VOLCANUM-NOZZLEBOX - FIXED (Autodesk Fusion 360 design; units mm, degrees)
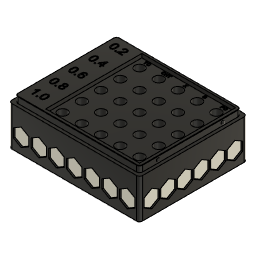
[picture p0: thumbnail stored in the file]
sketch "Sketch2" plane through (0, 0, 0) normal (0, 0, 1) x axis (1, 0, 0)
  line L1 (60, 10) -> (-10, 10)
  line L2 (60, -60) -> (60, 10)
  line L3 (-10, -60) -> (60, -60)
  line L4 (-10, 10) -> (-10, -60)
  horizontal L1
  vertical L2
  horizontal L3
  vertical L4
extrude "Extrude1" new body sketch "Sketch2" along normal blind 30
sketch "Sketch3" plane through (0, 0, 30) normal (0, 0, 1) x axis (-1, 0, 0)
  line L1 (-60, 60) -> (10, 60)
  line L2 (-60, -10) -> (-60, 60)
  line L3 (10, -10) -> (-60, -10)
  line L4 (10, 60) -> (10, -10)
  circle C1 centre (0, 0) radius 3.05
  circle C2 centre (-12.5, 0) radius 3.05
  circle C3 centre (-25, 0) radius 3.05
  circle C4 centre (-37.5, 0) radius 3.05
  circle C5 centre (-50, 0) radius 3.05
  circle C6 centre (0, 12.5) radius 3.05
  circle C7 centre (-12.5, 12.5) radius 3.05
  circle C8 centre (-25, 12.5) radius 3.05
  circle C9 centre (-37.5, 12.5) radius 3.05
  circle C10 centre (-50, 12.5) radius 3.05
  circle C11 centre (0, 25) radius 3.05
  circle C12 centre (-12.5, 25) radius 3.05
  circle C13 centre (-25, 25) radius 3.05
  circle C14 centre (-37.5, 25) radius 3.05
  circle C15 centre (-50, 25) radius 3.05
  circle C16 centre (0, 37.5) radius 3.05
  circle C17 centre (-12.5, 37.5) radius 3.05
  circle C18 centre (-25, 37.5) radius 3.05
  circle C19 centre (-37.5, 37.5) radius 3.05
  circle C20 centre (-50, 37.5) radius 3.05
  circle C21 centre (0, 50) radius 3.05
  circle C22 centre (-12.5, 50) radius 3.05
  circle C23 centre (-25, 50) radius 3.05
  circle C24 centre (-37.5, 50) radius 3.05
  circle C25 centre (-50, 50) radius 3.05
  point P1 (0, 0)
  point P6 (0, 0)
  coincident P1 P6
  dimension "d8" diameter C1 = 6.1
  dimension "d11" R-Pattern1-uDistance = -50
  dimension "d12" R-Pattern1-vDistance = 50
extrude "Extrude2" add of existing geometry blind 15
extrude "Extrude3" cut sketch "Sketch3" profile of C1 C2 C3 C4 C5 C6 C7 C8 C9 C10 C11 C12 C13 C14 C15 C16 C17 C18 C19 C20 C21 C22 C23 C24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 against normal blind 25
sketch "Sketch4" plane through (0, 0, 30) normal (0, 0, 1) x axis (-1, 0, 0)
  dimension "d17" = 5
  dimension "d18" = 5
  dimension "d19" = 5
  dimension "d20" = 5
  dimension "d21" = 5
  dimension "d22" = -2
extrude "Extrude4" cut sketch "Sketch4" against normal blind 5
sketch "Sketch5" plane through (0, 0, 30) normal (0, 0, 1) x axis (-1, 0, 0)
  line L1 (23, -8) -> (-58, -8)
  line L2 (23, 58) -> (23, -8)
  line L3 (-58, 58) -> (23, 58)
  line L4 (-58, -8) -> (-58, 58)
  line L5 (-60, -10) -> (25, -10)
  line L6 (-60, 60) -> (-60, -10)
  line L7 (25, 60) -> (-60, 60)
  line L8 (25, -10) -> (25, 60)
  circle C1 centre (-37.5, 0) radius 3.05
  circle C2 centre (-25, 0) radius 3.05
  circle C3 centre (-50, 25) radius 3.05
  circle C4 centre (-12.5, 25) radius 3.05
  circle C5 centre (-25, 37.5) radius 3.05
  circle C6 centre (-25, 50) radius 3.05
  circle C7 centre (-12.5, 50) radius 3.05
  circle C8 centre (-37.5, 37.5) radius 3.05
  circle C9 centre (0, 25) radius 3.05
  circle C10 centre (-37.5, 25) radius 3.05
  circle C11 centre (-12.5, 0) radius 3.05
  circle C12 centre (-37.5, 12.5) radius 3.05
  circle C13 centre (-50, 0) radius 3.05
  circle C14 centre (-25, 12.5) radius 3.05
  circle C15 centre (0, 12.5) radius 3.05
  circle C16 centre (-25, 25) radius 3.05
  circle C17 centre (-12.5, 37.5) radius 3.05
  circle C18 centre (-37.5, 50) radius 3.05
  circle C19 centre (0, 50) radius 3.05
  circle C20 centre (-50, 50) radius 3.05
  circle C21 centre (0, 37.5) radius 3.05
  circle C22 centre (-50, 37.5) radius 3.05
  circle C23 centre (0, 0) radius 3.05
  circle C24 centre (-12.5, 12.5) radius 3.05
  circle C25 centre (-50, 12.5) radius 3.05
  horizontal L5
  vertical L6
  horizontal L7
  vertical L8
extrude "Extrude5" new body sketch "Sketch5" along normal blind 8
move "Move1"
sketch "Sketch6" plane through (0, 0, 43) normal (0, 0, -1) x axis (1, 0, 0)
  line L1 (-25, 60) -> (60, 60)
  line L2 (-25, -10) -> (-25, 60)
  line L3 (60, -10) -> (-25, -10)
  line L4 (60, 60) -> (60, -10)
  line L5 (58, -8) -> (-23, -8)
  line L6 (58, 58) -> (58, -8)
  line L7 (-23, 58) -> (58, 58)
  line L8 (-23, -8) -> (-23, 58)
  dimension "d27" = -2
extrude "Extrude6" cut sketch "Sketch6" profile of L5 L6 L7 L8 against normal blind 5
extrude "Extrude7" add of existing geometry blind 1
extrude "Extrude8" cut sketch "Sketch4" against normal blind 1
sketch "Sketch7" plane through (0, 0, 51) normal (0, 0, 1) x axis (-1, 0, 0)
  line L1 (-60, 60) -> (25, 60)
  line L2 (-60, -10) -> (-60, 60)
  line L3 (25, -10) -> (-60, -10)
  line L4 (25, 60) -> (25, -10)
  line L5 (467.8571, 12.8867) -> (467.8571, 7.1133)
  line L6 (503.5714, 7.1133) -> (503.5714, 12.8867)
  line L7 (430, 100) -> (530, 100)
  line L8 (520, 4.2265) -> (515, 7.1133)
  line L9 (502.1428, 7.1133) -> (497.1429, 4.2265)
  line L10 (503.5714, 12.8867) -> (508.5714, 15.7735)
  line L11 (492.1429, 7.1133) -> (492.1429, 12.8867)
  line L12 (502.1428, 12.8867) -> (502.1428, 7.1133)
  line L13 (525, 27.1133) -> (520, 24.2265)
  line L14 (525, 7.1133) -> (520, 4.2265)
  line L15 (462.8571, 24.2265) -> (457.8572, 27.1133)
  line L16 (479.2857, 12.8867) -> (479.2857, 7.1133)
  line L17 (508.5714, 15.7735) -> (513.5714, 12.8867)
  line L18 (530, 0) -> (430, 0)
  line L19 (492.1429, 12.8867) -> (497.1429, 15.7735)
  line L20 (513.5714, 7.1133) -> (508.5714, 4.2265)
  line L21 (513.5714, 12.8867) -> (513.5714, 7.1133)
  line L22 (485.7143, 15.7735) -> (490.7143, 12.8867)
  line L23 (440, 15.7735) -> (445, 12.8867)
  line L24 (435, 7.1133) -> (435, 12.8867)
  line L25 (480.7143, 27.1133) -> (480.7143, 32.8867)
  line L26 (445, 7.1133) -> (440, 4.2265)
  line L27 (515, 12.8867) -> (520, 15.7735)
  line L28 (469.2857, 32.8867) -> (474.2857, 35.7735)
  line L29 (445, 12.8867) -> (445, 7.1133)
  line L30 (497.1429, 35.7735) -> (502.1428, 32.8867)
  line L31 (515, 7.1133) -> (515, 12.8867)
  line L32 (520, 35.7735) -> (525, 32.8867)
  line L33 (508.5714, 35.7735) -> (513.5714, 32.8867)
  line L34 (508.5714, 4.2265) -> (503.5714, 7.1133)
  line L35 (479.2857, 7.1133) -> (474.2857, 4.2265)
  line L36 (520, 15.7735) -> (525, 12.8867)
  line L37 (497.1429, 4.2265) -> (492.1429, 7.1133)
  line L38 (474.2857, 24.2265) -> (469.2857, 27.1133)
  line L39 (530, 100) -> (530, 0)
  line L40 (457.8572, 27.1133) -> (457.8572, 32.8867)
  line L41 (492.1429, 27.1133) -> (492.1429, 32.8867)
  line L42 (502.1428, 27.1133) -> (497.1429, 24.2265)
  line L43 (435, 12.8867) -> (440, 15.7735)
  line L44 (525, 12.8867) -> (525, 7.1133)
  line L45 (474.2857, 4.2265) -> (469.2857, 7.1133)
  line L46 (430, 0) -> (430, 100)
  line L47 (457.8572, 32.8867) -> (462.8571, 35.7735)
  line L48 (474.2857, 35.7735) -> (479.2857, 32.8867)
  line L49 (525, 32.8867) -> (525, 27.1133)
  line L50 (513.5714, 47.1133) -> (508.5714, 44.2265)
  line L51 (457.8572, 7.1133) -> (457.8572, 12.8867)
  line L52 (502.1428, 47.1133) -> (497.1429, 44.2265)
  line L53 (445, 32.8867) -> (445, 27.1133)
  line L54 (467.8571, 27.1133) -> (462.8571, 24.2265)
  line L55 (480.7143, 12.8867) -> (485.7143, 15.7735)
  line L56 (490.7143, 27.1133) -> (485.7143, 24.2265)
  line L57 (520, 24.2265) -> (515, 27.1133)
  line L58 (435, 47.1133) -> (435, 52.8867)
  line L59 (490.7143, 12.8867) -> (490.7143, 7.1133)
  line L60 (467.8571, 7.1133) -> (462.8571, 4.2265)
  line L61 (451.4286, 55.7735) -> (456.4286, 52.8867)
  line L62 (492.1429, 32.8867) -> (497.1429, 35.7735)
  line L63 (457.8572, 12.8867) -> (462.8571, 15.7735)
  line L64 (474.2857, 44.2265) -> (469.2857, 47.1133)
  line L65 (503.5714, 32.8867) -> (508.5714, 35.7735)
  line L66 (492.1429, 52.8867) -> (497.1429, 55.7735)
  line L67 (440, 44.2265) -> (435, 47.1133)
  line L68 (513.5714, 27.1133) -> (508.5714, 24.2265)
  line L69 (480.7143, 7.1133) -> (480.7143, 12.8867)
  line L70 (445, 52.8867) -> (445, 47.1133)
  line L71 (485.7143, 24.2265) -> (480.7143, 27.1133)
  line L72 (485.7143, 4.2265) -> (480.7143, 7.1133)
  line L73 (451.4286, 15.7735) -> (456.4286, 12.8867)
  line L74 (503.5714, 27.1133) -> (503.5714, 32.8867)
  line L75 (497.1429, 15.7735) -> (502.1428, 12.8867)
  line L76 (480.7143, 32.8867) -> (485.7143, 35.7735)
  line L77 (515, 27.1133) -> (515, 32.8867)
  line L78 (446.4286, 47.1133) -> (446.4286, 52.8867)
  line L79 (440, 4.2265) -> (435, 7.1133)
  line L80 (485.7143, 35.7735) -> (490.7143, 32.8867)
  line L81 (446.4286, 12.8867) -> (451.4286, 15.7735)
  line L82 (490.7143, 7.1133) -> (485.7143, 4.2265)
  line L83 (451.4286, 44.2265) -> (446.4286, 47.1133)
  line L84 (502.1428, 52.8867) -> (502.1428, 47.1133)
  line L85 (445, 47.1133) -> (440, 44.2265)
  line L86 (508.5714, 55.7735) -> (513.5714, 52.8867)
  line L87 (440, 55.7735) -> (445, 52.8867)
  line L88 (446.4286, 7.1133) -> (446.4286, 12.8867)
  line L89 (469.2857, 12.8867) -> (474.2857, 15.7735)
  line L90 (435, 52.8867) -> (440, 55.7735)
  line L91 (451.4286, 35.7735) -> (456.4286, 32.8867)
  line L92 (515, 52.8867) -> (520, 55.7735)
  line L93 (445, 27.1133) -> (440, 24.2265)
  line L94 (456.4286, 12.8867) -> (456.4286, 7.1133)
  line L95 (469.2857, 27.1133) -> (469.2857, 32.8867)
  line L96 (490.7143, 32.8867) -> (490.7143, 27.1133)
  line L97 (462.8571, 15.7735) -> (467.8571, 12.8867)
  line L98 (440, 24.2265) -> (435, 27.1133)
  line L99 (469.2857, 7.1133) -> (469.2857, 12.8867)
  line L100 (515, 32.8867) -> (520, 35.7735)
  line L101 (508.5714, 24.2265) -> (503.5714, 27.1133)
  line L102 (513.5714, 32.8867) -> (513.5714, 27.1133)
  line L103 (479.2857, 32.8867) -> (479.2857, 27.1133)
  line L104 (508.5714, 44.2265) -> (503.5714, 47.1133)
  line L105 (467.8571, 47.1133) -> (462.8571, 44.2265)
  line L106 (451.4286, 4.2265) -> (446.4286, 7.1133)
  line L107 (497.1429, 24.2265) -> (492.1429, 27.1133)
  line L108 (462.8571, 4.2265) -> (457.8572, 7.1133)
  line L109 (502.1428, 32.8867) -> (502.1428, 27.1133)
  line L110 (456.4286, 7.1133) -> (451.4286, 4.2265)
  line L111 (474.2857, 15.7735) -> (479.2857, 12.8867)
  line L112 (479.2857, 27.1133) -> (474.2857, 24.2265)
  line L113 (492.1429, 47.1133) -> (492.1429, 52.8867)
  line L114 (513.5714, 67.1133) -> (508.5714, 64.2265)
  line L115 (485.7143, 44.2265) -> (480.7143, 47.1133)
  line L116 (513.5714, 72.8867) -> (513.5714, 67.1133)
  line L117 (525, 72.8867) -> (525, 67.1133)
  line L118 (469.2857, 52.8867) -> (474.2857, 55.7735)
  line L119 (520, 44.2265) -> (515, 47.1133)
  line L120 (520, 64.2265) -> (515, 67.1133)
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fillet "Fillet1" radius 2
chamfer "Chamfer1" distance 0.5
fillet "Fillet2" radius 2
extrude "Extrude9" cut sketch "Sketch7" against normal blind 1
sketch "Sketch8" plane through (0, 0, 51) normal (0, 0, 1) x axis (-1, 0, 0)
  dimension "d41" = 5
  dimension "d42" = 5
  dimension "d43" = 5
  dimension "d44" = 5
  dimension "d45" = 5
  dimension "d46" = 5
  dimension "d47" = 5
  dimension "d48" = 5
  dimension "d49" = 5
  dimension "d50" = 5
  dimension "d51" = 5
  dimension "d52" = 5
  dimension "d53" = 5
  dimension "d54" = 5
  dimension "d55" = 5
  dimension "d56" = 5
extrude "Extrude10" cut sketch "Sketch8" against normal blind 1
chamfer "Chamfer2" distance 0.4
chamfer "Chamfer3" distance 0.2
chamfer "Chamfer4" distance 0.2
sketch "Sketch9" plane through (0, -60, 0) normal (0, -1, 0) x axis (1, 0, 0)
  line L1 (58, 0.4) -> (-23, 0.4)
  line L2 (58, 26) -> (58, 0.4)
  line L3 (-23, 26) -> (58, 26)
  line L4 (-23, 0.4) -> (-23, 26)
  line L5 (480.7143, 7.1133) -> (480.7143, 12.8867)
  line L6 (474.2857, 4.2265) -> (469.2857, 7.1133)
  line L7 (469.2857, 7.1133) -> (469.2857, 12.8867)
  line L8 (469.2857, 12.8867) -> (474.2857, 15.7735)
  line L9 (485.7143, 15.7735) -> (490.7143, 12.8867)
  line L10 (490.7143, 12.8867) -> (490.7143, 7.1133)
  line L11 (525, 7.1133) -> (520, 4.2265)
  line L12 (503.5714, 12.8867) -> (508.5714, 15.7735)
  line L13 (520, 4.2265) -> (515, 7.1133)
  line L14 (469.2857, 32.8867) -> (474.2857, 35.7735)
  line L15 (503.5714, 7.1133) -> (503.5714, 12.8867)
  line L16 (467.8571, 32.8867) -> (467.8571, 27.1133)
  line L17 (508.5714, 4.2265) -> (503.5714, 7.1133)
  line L18 (479.2857, 32.8867) -> (479.2857, 27.1133)
  line L19 (497.1429, 24.2265) -> (492.1429, 27.1133)
  line L20 (462.8571, 35.7735) -> (467.8571, 32.8867)
  line L21 (451.4286, 4.2265) -> (446.4286, 7.1133)
  line L22 (445, 7.1133) -> (440, 4.2265)
  line L23 (503.5714, 32.8867) -> (508.5714, 35.7735)
  line L24 (446.4286, 7.1133) -> (446.4286, 12.8867)
  line L25 (462.8571, 24.2265) -> (457.8572, 27.1133)
  line L26 (502.1428, 27.1133) -> (497.1429, 24.2265)
  line L27 (520, 24.2265) -> (515, 27.1133)
  line L28 (446.4286, 32.8867) -> (451.4286, 35.7735)
  line L29 (513.5714, 27.1133) -> (508.5714, 24.2265)
  line L30 (435, 7.1133) -> (435, 12.8867)
  line L31 (502.1428, 12.8867) -> (502.1428, 7.1133)
  line L32 (520, 35.7735) -> (525, 32.8867)
  line L33 (457.8572, 12.8867) -> (462.8571, 15.7735)
  line L34 (513.5714, 12.8867) -> (513.5714, 7.1133)
  line L35 (525, 27.1133) -> (520, 24.2265)
  line L36 (492.1429, 7.1133) -> (492.1429, 12.8867)
  line L37 (467.8571, 7.1133) -> (462.8571, 4.2265)
  line L38 (435, 12.8867) -> (440, 15.7735)
  line L39 (490.7143, 32.8867) -> (490.7143, 27.1133)
  line L40 (430, 100) -> (530, 100)
  line L41 (497.1429, 35.7735) -> (502.1428, 32.8867)
  line L42 (435, 32.8867) -> (440, 35.7735)
  line L43 (485.7143, 24.2265) -> (480.7143, 27.1133)
  line L44 (456.4286, 7.1133) -> (451.4286, 4.2265)
  line L45 (480.7143, 32.8867) -> (485.7143, 35.7735)
  line L46 (457.8572, 7.1133) -> (457.8572, 12.8867)
  line L47 (457.8572, 27.1133) -> (457.8572, 32.8867)
  line L48 (467.8571, 27.1133) -> (462.8571, 24.2265)
  line L49 (446.4286, 27.1133) -> (446.4286, 32.8867)
  line L50 (479.2857, 7.1133) -> (474.2857, 4.2265)
  line L51 (457.8572, 32.8867) -> (462.8571, 35.7735)
  line L52 (502.1428, 32.8867) -> (502.1428, 27.1133)
  line L53 (451.4286, 24.2265) -> (446.4286, 27.1133)
  line L54 (479.2857, 27.1133) -> (474.2857, 24.2265)
  line L55 (502.1428, 7.1133) -> (497.1429, 4.2265)
  line L56 (490.7143, 27.1133) -> (485.7143, 24.2265)
  line L57 (467.8571, 12.8867) -> (467.8571, 7.1133)
  line L58 (456.4286, 12.8867) -> (456.4286, 7.1133)
  line L59 (480.7143, 12.8867) -> (485.7143, 15.7735)
  line L60 (515, 7.1133) -> (515, 12.8867)
  line L61 (520, 15.7735) -> (525, 12.8867)
  line L62 (445, 12.8867) -> (445, 7.1133)
  line L63 (497.1429, 4.2265) -> (492.1429, 7.1133)
  line L64 (492.1429, 12.8867) -> (497.1429, 15.7735)
  line L65 (525, 32.8867) -> (525, 27.1133)
  line L66 (430, 0) -> (430, 100)
  line L67 (497.1429, 15.7735) -> (502.1428, 12.8867)
  line L68 (515, 12.8867) -> (520, 15.7735)
  line L69 (456.4286, 32.8867) -> (456.4286, 27.1133)
  line L70 (513.5714, 7.1133) -> (508.5714, 4.2265)
  line L71 (530, 100) -> (530, 0)
  line L72 (451.4286, 35.7735) -> (456.4286, 32.8867)
  line L73 (525, 12.8867) -> (525, 7.1133)
  line L74 (530, 0) -> (430, 0)
  line L75 (508.5714, 15.7735) -> (513.5714, 12.8867)
  line L76 (479.2857, 12.8867) -> (479.2857, 7.1133)
  line L77 (456.4286, 27.1133) -> (451.4286, 24.2265)
  line L78 (467.8571, 52.8867) -> (467.8571, 47.1133)
  line L79 (485.7143, 35.7735) -> (490.7143, 32.8867)
  line L80 (445, 47.1133) -> (440, 44.2265)
  line L81 (445, 52.8867) -> (445, 47.1133)
  line L82 (440, 24.2265) -> (435, 27.1133)
  line L83 (440, 55.7735) -> (445, 52.8867)
  line L84 (469.2857, 27.1133) -> (469.2857, 32.8867)
  line L85 (503.5714, 27.1133) -> (503.5714, 32.8867)
  line L86 (502.1428, 47.1133) -> (497.1429, 44.2265)
  line L87 (492.1429, 27.1133) -> (492.1429, 32.8867)
  line L88 (513.5714, 72.8867) -> (513.5714, 67.1133)
  line L89 (508.5714, 24.2265) -> (503.5714, 27.1133)
  line L90 (451.4286, 55.7735) -> (456.4286, 52.8867)
  line L91 (525, 47.1133) -> (520, 44.2265)
  line L92 (474.2857, 55.7735) -> (479.2857, 52.8867)
  line L93 (445, 32.8867) -> (445, 27.1133)
  line L94 (474.2857, 44.2265) -> (469.2857, 47.1133)
  line L95 (480.7143, 52.8867) -> (485.7143, 55.7735)
  line L96 (469.2857, 47.1133) -> (469.2857, 52.8867)
  line L97 (462.8571, 15.7735) -> (467.8571, 12.8867)
  line L98 (513.5714, 52.8867) -> (513.5714, 47.1133)
  line L99 (520, 55.7735) -> (525, 52.8867)
  line L100 (515, 32.8867) -> (520, 35.7735)
  line L101 (446.4286, 12.8867) -> (451.4286, 15.7735)
  line L102 (474.2857, 35.7735) -> (479.2857, 32.8867)
  line L103 (457.8572, 47.1133) -> (457.8572, 52.8867)
  line L104 (456.4286, 52.8867) -> (456.4286, 47.1133)
  line L105 (456.4286, 47.1133) -> (451.4286, 44.2265)
  line L106 (525, 67.1133) -> (520, 64.2265)
  line L107 (503.5714, 47.1133) -> (503.5714, 52.8867)
  line L108 (497.1429, 55.7735) -> (502.1428, 52.8867)
  line L109 (490.7143, 47.1133) -> (485.7143, 44.2265)
  line L110 (462.8571, 44.2265) -> (457.8572, 47.1133)
  line L111 (451.4286, 44.2265) -> (446.4286, 47.1133)
  line L112 (508.5714, 44.2265) -> (503.5714, 47.1133)
  line L113 (485.7143, 55.7735) -> (490.7143, 52.8867)
  line L114 (492.1429, 47.1133) -> (492.1429, 52.8867)
  line L115 (490.7143, 52.8867) -> (490.7143, 47.1133)
  line L116 (435, 52.8867) -> (440, 55.7735)
  line L117 (457.8572, 52.8867) -> (462.8571, 55.7735)
  line L118 (469.2857, 52.8867) -> (474.2857, 55.7735)
  line L119 (485.7143, 44.2265) -> (480.7143, 47.1133)
  line L120 (451.4286, 15.7735) -> (456.4286, 12.8867)
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  dimension "d64" R-Pattern1-uDistance = 69
  dimension "d65" R-Pattern1-vDistance = 0
extrude "Extrude11" cut sketch "Sketch9" against normal blind 1
sketch "Sketch10" plane through (-25, 0, 0) normal (-1, 0, 0) x axis (0, -1, 0)
  line L1 (58, 0.4) -> (-8, 0.4)
  line L2 (58, 26) -> (58, 0.4)
  line L3 (-8, 26) -> (58, 26)
  line L4 (-8, 0.4) -> (-8, 26)
  line L5 (-2, 15.7735) -> (3, 12.8867)
  line L6 (-7, 12.8867) -> (-2, 15.7735)
  line L7 (-7, 7.1133) -> (-7, 12.8867)
  line L8 (-2, 4.2265) -> (-7, 7.1133)
  line L9 (3, 7.1133) -> (-2, 4.2265)
  line L10 (3, 12.8867) -> (3, 7.1133)
  line L11 (13.8, 12.8867) -> (13.8, 7.1133)
  line L12 (8.8, 15.7735) -> (13.8, 12.8867)
  line L13 (3.8, 12.8867) -> (8.8, 15.7735)
  line L14 (3.8, 7.1133) -> (3.8, 12.8867)
  line L15 (8.8, 4.2265) -> (3.8, 7.1133)
  line L16 (13.8, 7.1133) -> (8.8, 4.2265)
  line L17 (24.6, 12.8867) -> (24.6, 7.1133)
  line L18 (19.6, 15.7735) -> (24.6, 12.8867)
  line L19 (14.6, 12.8867) -> (19.6, 15.7735)
  line L20 (14.6, 7.1133) -> (14.6, 12.8867)
  line L21 (19.6, 4.2265) -> (14.6, 7.1133)
  line L22 (24.6, 7.1133) -> (19.6, 4.2265)
  line L23 (35.4, 12.8867) -> (35.4, 7.1133)
  line L24 (30.4, 15.7735) -> (35.4, 12.8867)
  line L25 (25.4, 12.8867) -> (30.4, 15.7735)
  line L26 (25.4, 7.1133) -> (25.4, 12.8867)
  line L27 (30.4, 4.2265) -> (25.4, 7.1133)
  line L28 (35.4, 7.1133) -> (30.4, 4.2265)
  line L29 (46.2, 12.8867) -> (46.2, 7.1133)
  line L30 (41.2, 15.7735) -> (46.2, 12.8867)
  line L31 (36.2, 12.8867) -> (41.2, 15.7735)
  line L32 (36.2, 7.1133) -> (36.2, 12.8867)
  line L33 (41.2, 4.2265) -> (36.2, 7.1133)
  line L34 (46.2, 7.1133) -> (41.2, 4.2265)
  line L35 (57, 12.8867) -> (57, 7.1133)
  line L36 (52, 15.7735) -> (57, 12.8867)
  line L37 (47, 12.8867) -> (52, 15.7735)
  line L38 (47, 7.1133) -> (47, 12.8867)
  line L39 (52, 4.2265) -> (47, 7.1133)
  line L40 (57, 7.1133) -> (52, 4.2265)
  dimension "d70" R-Pattern1-uDistance = 54
  dimension "d71" R-Pattern1-vDistance = 0
extrude "Extrude12" cut sketch "Sketch10" profile of L5 L6 L7 L8 L9 L10 L11 L12 L13 L14 L15 L16 L17 L18 L19 L20 L21 L22 L23 L24 L25 L26 L27 L28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 against normal blind 1
sketch "Sketch11" plane through (0, 10, 0) normal (0, 1, 0) x axis (-1, 0, 0)
  line L1 (23, 0.4) -> (-58, 0.4)
  line L2 (23, 26) -> (23, 0.4)
  line L3 (-58, 26) -> (23, 26)
  line L4 (-58, 0.4) -> (-58, 26)
  line L5 (-52, 15.7735) -> (-47, 12.8867)
  line L6 (-57, 12.8867) -> (-52, 15.7735)
  line L7 (-57, 7.1133) -> (-57, 12.8867)
  line L8 (-52, 4.2265) -> (-57, 7.1133)
  line L9 (-47, 7.1133) -> (-52, 4.2265)
  line L10 (-47, 12.8867) -> (-47, 7.1133)
  line L11 (-35.5, 12.8867) -> (-35.5, 7.1133)
  line L12 (-40.5, 15.7735) -> (-35.5, 12.8867)
  line L13 (-45.5, 12.8867) -> (-40.5, 15.7735)
  line L14 (-45.5, 7.1133) -> (-45.5, 12.8867)
  line L15 (-40.5, 4.2265) -> (-45.5, 7.1133)
  line L16 (-35.5, 7.1133) -> (-40.5, 4.2265)
  line L17 (-24, 12.8867) -> (-24, 7.1133)
  line L18 (-29, 15.7735) -> (-24, 12.8867)
  line L19 (-34, 12.8867) -> (-29, 15.7735)
  line L20 (-34, 7.1133) -> (-34, 12.8867)
  line L21 (-29, 4.2265) -> (-34, 7.1133)
  line L22 (-24, 7.1133) -> (-29, 4.2265)
  line L23 (-12.5, 12.8867) -> (-12.5, 7.1133)
  line L24 (-17.5, 15.7735) -> (-12.5, 12.8867)
  line L25 (-22.5, 12.8867) -> (-17.5, 15.7735)
  line L26 (-22.5, 7.1133) -> (-22.5, 12.8867)
  line L27 (-17.5, 4.2265) -> (-22.5, 7.1133)
  line L28 (-12.5, 7.1133) -> (-17.5, 4.2265)
  line L29 (-1, 12.8867) -> (-1, 7.1133)
  line L30 (-6, 15.7735) -> (-1, 12.8867)
  line L31 (-11, 12.8867) -> (-6, 15.7735)
  line L32 (-11, 7.1133) -> (-11, 12.8867)
  line L33 (-6, 4.2265) -> (-11, 7.1133)
  line L34 (-1, 7.1133) -> (-6, 4.2265)
  line L35 (10.5, 12.8867) -> (10.5, 7.1133)
  line L36 (5.5, 15.7735) -> (10.5, 12.8867)
  line L37 (0.5, 12.8867) -> (5.5, 15.7735)
  line L38 (0.5, 7.1133) -> (0.5, 12.8867)
  line L39 (5.5, 4.2265) -> (0.5, 7.1133)
  line L40 (10.5, 7.1133) -> (5.5, 4.2265)
  line L41 (22, 12.8867) -> (22, 7.1133)
  line L42 (17, 15.7735) -> (22, 12.8867)
  line L43 (12, 12.8867) -> (17, 15.7735)
  line L44 (12, 7.1133) -> (12, 12.8867)
  line L45 (17, 4.2265) -> (12, 7.1133)
  line L46 (22, 7.1133) -> (17, 4.2265)
  dimension "d76" R-Pattern1-uDistance = 69
  dimension "d77" R-Pattern1-vDistance = 0
extrude "Extrude13" cut sketch "Sketch11" profile of L5 L6 L7 L8 L9 L10 L11 L12 L13 L14 L15 L16 L17 L18 L19 L20 L21 L22 L23 L24 L25 L26 L27 L28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 against normal blind 1
sketch "Sketch12" plane through (60, 0, 0) normal (1, 0, 0) x axis (0, 1, 0)
  line L1 (8, 0.4) -> (-58, 0.4)
  line L2 (8, 26) -> (8, 0.4)
  line L3 (-58, 26) -> (8, 26)
  line L4 (-58, 0.4) -> (-58, 26)
  line L5 (-52, 15.7735) -> (-47, 12.8867)
  line L6 (-57, 12.8867) -> (-52, 15.7735)
  line L7 (-57, 7.1133) -> (-57, 12.8867)
  line L8 (-52, 4.2265) -> (-57, 7.1133)
  line L9 (-47, 7.1133) -> (-52, 4.2265)
  line L10 (-47, 12.8867) -> (-47, 7.1133)
  line L11 (-46.2, 12.8867) -> (-41.2, 15.7735)
  line L12 (-41.2, 15.7735) -> (-36.2, 12.8867)
  line L13 (-36.2, 12.8867) -> (-36.2, 7.1133)
  line L14 (-36.2, 7.1133) -> (-41.2, 4.2265)
  line L15 (-41.2, 4.2265) -> (-46.2, 7.1133)
  line L16 (-46.2, 7.1133) -> (-46.2, 12.8867)
  line L17 (-35.4, 12.8867) -> (-30.4, 15.7735)
  line L18 (-30.4, 15.7735) -> (-25.4, 12.8867)
  line L19 (-25.4, 12.8867) -> (-25.4, 7.1133)
  line L20 (-25.4, 7.1133) -> (-30.4, 4.2265)
  line L21 (-30.4, 4.2265) -> (-35.4, 7.1133)
  line L22 (-35.4, 7.1133) -> (-35.4, 12.8867)
  line L23 (-24.6, 12.8867) -> (-19.6, 15.7735)
  line L24 (-19.6, 15.7735) -> (-14.6, 12.8867)
  line L25 (-14.6, 12.8867) -> (-14.6, 7.1133)
  line L26 (-14.6, 7.1133) -> (-19.6, 4.2265)
  line L27 (-19.6, 4.2265) -> (-24.6, 7.1133)
  line L28 (-24.6, 7.1133) -> (-24.6, 12.8867)
  line L29 (-13.8, 12.8867) -> (-8.8, 15.7735)
  line L30 (-8.8, 15.7735) -> (-3.8, 12.8867)
  line L31 (-3.8, 12.8867) -> (-3.8, 7.1133)
  line L32 (-3.8, 7.1133) -> (-8.8, 4.2265)
  line L33 (-8.8, 4.2265) -> (-13.8, 7.1133)
  line L34 (-13.8, 7.1133) -> (-13.8, 12.8867)
  line L35 (-3, 12.8867) -> (2, 15.7735)
  line L36 (2, 15.7735) -> (7, 12.8867)
  line L37 (7, 12.8867) -> (7, 7.1133)
  line L38 (7, 7.1133) -> (2, 4.2265)
  line L39 (2, 4.2265) -> (-3, 7.1133)
  line L40 (-3, 7.1133) -> (-3, 12.8867)
  dimension "d82" R-Pattern1-uDistance = 54
  dimension "d83" R-Pattern1-vDistance = 0
extrude "Extrude14" cut sketch "Sketch12" profile of L5 L6 L7 L8 L9 L10 L11 L12 L13 L14 L15 L16 L17 L18 L19 L20 L21 L22 L23 L24 L25 L26 L27 L28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 against normal blind 1
sketch "Sketch13" plane through (-23, 0, 0) normal (-1, 0, 0) x axis (0, -1, 0)
  line L1 (-6, 29.8) -> (56, 29.8)
  line L2 (-6, 26) -> (-6, 29.8)
  line L3 (56, 26) -> (-6, 26)
  line L4 (56, 29.8) -> (56, 26)
  line L5 (4, 27.9) -> (-6, 27.9)
  line L6 (46, 27.9) -> (56, 27.9)
  circle C1 centre (4, 27.9) radius 1
  circle C2 centre (46, 27.9) radius 1
  point P6 (-6, 27.9)
  point P8 (56, 27.9)
  point P7 (4, 27.9)
  point P10 (4, 27.9)
  point P9 (46, 27.9)
  point P11 (46, 27.9)
  midpoint L2 P6
  perpendicular L2 L5
  midpoint L4 P8
  perpendicular L4 L6
  coincident P7 P10
  coincident P9 P11
  dimension "d86" distance P8 P9 = 10
  dimension "d87" diameter C1 = 2
  dimension "d88" diameter C2 = 2
extrude "Extrude15" add sketch "Sketch13" profile of C1 C2 along normal blind 1
fillet "Fillet3" radius 1
sketch "Sketch14" plane through (58, 0, 0) normal (1, 0, 0) x axis (0, 1, 0)
  line L1 (-56, 29.8) -> (6, 29.8)
  line L2 (-56, 26) -> (-56, 29.8)
  line L3 (6, 26) -> (-56, 26)
  line L4 (6, 29.8) -> (6, 26)
  line L5 (-46, 27.9) -> (-56, 27.9)
  line L6 (-4, 27.9) -> (6, 27.9)
  circle C1 centre (-46, 27.9) radius 1
  circle C2 centre (-4, 27.9) radius 1
  point P6 (-56, 27.9)
  point P8 (6, 27.9)
  point P7 (-46, 27.9)
  point P10 (-46, 27.9)
  point P9 (-4, 27.9)
  point P11 (-4, 27.9)
  midpoint L2 P6
  perpendicular L2 L5
  midpoint L4 P8
  perpendicular L4 L6
  coincident P7 P10
  coincident P9 P11
  dimension "d93" diameter C1 = 2
  dimension "d94" diameter C2 = 2
extrude "Extrude16" add sketch "Sketch14" profile of C1 C2 along normal blind 1
fillet "Fillet4" radius 1
move "Move2"
combine "Combine1"
move "Move3"
move "Move4"
move "Move5"
move "Move6"
move "Move7"
move "Move8"
move "Move9"
sketch "Sketch15" plane through (0, 0, 0) normal (0, 0, -1) x axis (1, 0, 0)
  line L1 (-23, 59.6) -> (58, 59.6)
  line L2 (-24.6, -8) -> (-24.6, 58)
  line L3 (58, -9.6) -> (-23, -9.6)
  line L4 (59.6, 58) -> (59.6, -8)
  curve K1 (1.2773, -1.7533) -> (-0.782, -5.4718)
  curve K2 (1.3711, -1.6298) -> (1.2773, -1.7533)
  curve K3 (1.4945, -3.1508) -> (1.3711, -1.6298)
  curve K4 (2.8526, -4.494) -> (1.4945, -3.1508)
  curve K5 (4.1316, -4.2026) -> (2.8526, -4.494)
  curve K6 (3.9143, -1.8521) -> (4.1316, -4.2026)
  curve K7 (3.6723, -0.7558) -> (3.9143, -1.8521)
  curve K8 (3.3958, 0.1973) -> (3.6723, -0.7558)
  curve K9 (3.2328, 1.0121) -> (3.3958, 0.1973)
  curve K10 (3.1982, 1.4269) -> (3.2328, 1.0121)
  curve K11 (3.0056, 1.4911) -> (3.1982, 1.4269)
  curve K12 (2.7439, 1.3084) -> (3.0056, 1.4911)
  curve K13 (2.6303, 0.859) -> (2.7439, 1.3084)
  curve K14 (2.8772, -0.099) -> (2.6303, 0.859)
  curve K15 (3.1242, -1.0126) -> (2.8772, -0.099)
  curve K16 (3.3513, -2.0397) -> (3.1242, -1.0126)
  curve K17 (3.618, -3.6446) -> (3.3513, -2.0397)
  line L5 (3.618, -3.9014) -> (3.618, -3.6446)
  line L6 (2.8575, -3.9014) -> (3.618, -3.9014)
  line L7 (2.1019, -3.9014) -> (2.8575, -3.9014)
  line L8 (2.0723, -2.7804) -> (2.1019, -3.9014)
  curve K18 (1.9933, -1.4768) -> (2.0723, -2.7804)
  curve K19 (1.1736, -1.0373) -> (1.9933, -1.4768)
  curve K20 (0.6205, -1.8076) -> (1.1736, -1.0373)
  curve K21 (-1.098, -4.8644) -> (0.6205, -1.8076)
  line L9 (-1.1968, -4.9878) -> (-1.098, -4.8644)
  line L10 (-1.4931, -4.7508) -> (-1.1968, -4.9878)
  curve K22 (-3.2116, -3.3187) -> (-1.4931, -4.7508)
  curve K23 (-2.8807, -2.4693) -> (-3.2116, -3.3187)
  curve K24 (-2.456, -1.7039) -> (-2.8807, -2.4693)
  curve K25 (-0.9153, 2.0146) -> (-2.456, -1.7039)
  curve K26 (-0.6832, 2.5923) -> (-0.9153, 2.0146)
  curve K27 (-1.9622, 2.3997) -> (-0.6832, 2.5923)
  curve K28 (-5.4683, 1.422) -> (-1.9622, 2.3997)
  curve K29 (-5.9622, 1.1849) -> (-5.4683, 1.422)
  curve K30 (-6.1004, 1.4664) -> (-5.9622, 1.1849)
  curve K31 (-6.293, 3.2738) -> (-6.1004, 1.4664)
  curve K32 (-5.0239, 3.896) -> (-6.293, 3.2738)
  curve K33 (-4.135, 4.0738) -> (-5.0239, 3.896)
  curve K34 (-3.177, 4.2219) -> (-4.135, 4.0738)
  curve K35 (-2.5054, 4.296) -> (-3.177, 4.2219)
  curve K36 (-1.0881, 4.617) -> (-2.5054, 4.296)
  curve K37 (1.3908, 7.1552) -> (-1.0881, 4.617)
  curve K38 (2.0328, 8.2861) -> (1.3908, 7.1552)
  curve K39 (3.055, 10.0046) -> (2.0328, 8.2861)
  curve K40 (3.4698, 10.7305) -> (3.055, 10.0046)
  curve K41 (3.8353, 11.1355) -> (3.4698, 10.7305)
  curve K42 (5.8649, 11.5404) -> (3.8353, 11.1355)
  curve K43 (7.1735, 11.8712) -> (5.8649, 11.5404)
  curve K44 (8.2895, 11.9256) -> (7.1735, 11.8712)
  curve K45 (7.3611, 10.1725) -> (8.2895, 11.9256)
  curve K46 (6.3933, 8.4145) -> (7.3611, 10.1725)
  curve K47 (5.8797, 7.2293) -> (6.3933, 8.4145)
  curve K48 (6.0031, 6.9725) -> (5.8797, 7.2293)
  curve K49 (6.255, 7.0318) -> (6.0031, 6.9725)
  curve K50 (6.9266, 8.1577) -> (6.255, 7.0318)
  curve K51 (8.3834, 10.7651) -> (6.9266, 8.1577)
  curve K52 (8.8327, 12.3651) -> (8.3834, 10.7651)
  curve K53 (7.2476, 12.4984) -> (8.8327, 12.3651)
  curve K54 (6.4278, 12.2811) -> (7.2476, 12.4984)
  curve K55 (4.8229, 11.9206) -> (6.4278, 12.2811)
  curve K56 (1.8303, 12.0145) -> (4.8229, 11.9206)
  curve K57 (1.3958, 12.8638) -> (1.8303, 12.0145)
  curve K58 (2.5711, 15.3576) -> (1.3958, 12.8638)
  curve K59 (5.0698, 18.4094) -> (2.5711, 15.3576)
  curve K60 (5.0599, 18.9576) -> (5.0698, 18.4094)
  curve K61 (4.2254, 18.4094) -> (5.0599, 18.9576)
  curve K62 (2.1118, 15.728) -> (4.2254, 18.4094)
  curve K63 (0.902, 13.5009) -> (2.1118, 15.728)
  curve K64 (0.8526, 12.3749) -> (0.902, 13.5009)
  curve K65 (0.6402, 12.1675) -> (0.8526, 12.3749)
  curve K66 (-3.4338, 9.4071) -> (0.6402, 12.1675)
  curve K67 (-4.7622, 7.8268) -> (-3.4338, 9.4071)
  curve K68 (-5.7597, 5.7775) -> (-4.7622, 7.8268)
  curve K69 (-6.2338, 4.6713) -> (-5.7597, 5.7775)
  curve K70 (-6.7473, 5.6343) -> (-6.2338, 4.6713)
  curve K71 (-6.8757, 9.6095) -> (-6.7473, 5.6343)
  curve K72 (-6.0757, 11.9898) -> (-6.8757, 9.6095)
  curve K73 (-4.8313, 13.7725) -> (-6.0757, 11.9898)
  curve K74 (1.2229, 16.4984) -> (-4.8313, 13.7725)
  line L11 (1.8896, 16.6564) -> (1.2229, 16.4984)
  line L12 (1.86, 16.8342) -> (1.8896, 16.6564)
  curve K75 (1.8106, 17.0317) -> (1.86, 16.8342)
  curve K76 (0.8674, 16.8144) -> (1.8106, 17.0317)
  curve K77 (-3.6412, 15.1403) -> (0.8674, 16.8144)
  curve K78 (-6.2041, 12.5823) -> (-3.6412, 15.1403)
  curve K79 (-6.5893, 12.1577) -> (-6.2041, 12.5823)
  curve K80 (-7.6708, 12.9675) -> (-6.5893, 12.1577)
  curve K81 (-7.0338, 16.1872) -> (-7.6708, 12.9675)
  curve K82 (-3.1918, 19.0317) -> (-7.0338, 16.1872)
  curve K83 (0.0872, 19.723) -> (-3.1918, 19.0317)
  curve K84 (1.2674, 19.6637) -> (0.0872, 19.723)
  curve K85 (1.5982, 19.6391) -> (1.2674, 19.6637)
  curve K86 (1.6575, 19.8366) -> (1.5982, 19.6391)
  line L13 (1.6871, 19.9897) -> (1.6575, 19.8366)
  line L14 (1.3316, 20.0588) -> (1.6871, 19.9897)
  curve K87 (0.0378, 20.1181) -> (1.3316, 20.0588)
  curve K88 (-1.5227, 19.9847) -> (0.0378, 20.1181)
  curve K89 (-4.9745, 18.5675) -> (-1.5227, 19.9847)
  line L15 (-5.6165, 18.1872) -> (-4.9745, 18.5675)
  line L16 (-5.8535, 18.2959) -> (-5.6165, 18.1872)
  curve K90 (-6.4807, 19.3181) -> (-5.8535, 18.2959)
  curve K91 (-5.6115, 20.9724) -> (-6.4807, 19.3181)
  curve K92 (0.9069, 22.6217) -> (-5.6115, 20.9724)
  curve K93 (1.781, 22.039) -> (0.9069, 22.6217)
  curve K94 (5.297, 19.4712) -> (1.781, 22.039)
  curve K95 (12.7537, 22.518) -> (5.297, 19.4712)
  curve K96 (16.3388, 26.1575) -> (12.7537, 22.518)
  curve K97 (16.7191, 27.2093) -> (16.3388, 26.1575)
  curve K98 (16.4425, 27.2982) -> (16.7191, 27.2093)
  curve K99 (16.1759, 27.2637) -> (16.4425, 27.2982)
  curve K100 (14.3388, 24.597) -> (16.1759, 27.2637)
  curve K101 (5.2723, 20.0637) -> (14.3388, 24.597)
  curve K102 (3.0847, 20.8242) -> (5.2723, 20.0637)
  curve K103 (2.3489, 22.1724) -> (3.0847, 20.8242)
  curve K104 (2.3538, 24.8637) -> (2.3489, 22.1724)
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extrude "Extrude17" cut sketch "Sketch15" against normal blind 1
sketch "Sketch16" plane through (0, 0, 30) normal (0, 0, 1) x axis (-1, 0, 0)
  curve K1 (12.9263, 0.41) -> (12.6671, 0.0774)
  line L1 (10.4741, 0.41) -> (12.9263, 0.41)
  line L2 (10.4741, 1) -> (10.4741, 0.41)
  line L3 (13.779, 1) -> (10.4741, 1)
  curve K2 (13.7074, 0.5737) -> (13.779, 1)
  curve K3 (13.3032, -0.0914) -> (13.7074, 0.5737)
  curve K4 (12.5, -0.8486) -> (13.3032, -0.0914)
  curve K5 (11.3984, -1.9076) -> (12.5, -0.8486)
  curve K6 (11.1119, -2.646) -> (11.3984, -1.9076)
  curve K7 (11.3728, -3.2616) -> (11.1119, -2.646)
  curve K8 (12.0532, -3.5123) -> (11.3728, -3.2616)
  curve K9 (12.7626, -3.2462) -> (12.0532, -3.5123)
  curve K10 (13.0321, -2.5095) -> (12.7626, -3.2462)
  line L4 (13.663, -2.5744) -> (13.0321, -2.5095)
  curve K11 (13.1753, -3.6504) -> (13.663, -2.5744)
  curve K12 (12.0396, -4.0205) -> (13.1753, -3.6504)
  curve K13 (10.9004, -3.6214) -> (12.0396, -4.0205)
  curve K14 (10.4809, -2.6323) -> (10.9004, -3.6214)
  curve K15 (10.6037, -2.0423) -> (10.4809, -2.6323)
  curve K16 (11.0113, -1.4318) -> (10.6037, -2.0423)
  curve K17 (11.9577, -0.5518) -> (11.0113, -1.4318)
  curve K18 (12.6671, 0.0774) -> (11.9577, -0.5518)
  curve K19 (18.9418, 14.0668) -> (17.8061, 14.5853)
  curve K20 (19.4364, 12.0341) -> (18.9418, 14.0668)
  curve K21 (19.2539, 10.6068) -> (19.4364, 12.0341)
  curve K22 (18.7116, 9.7729) -> (19.2539, 10.6068)
  curve K23 (17.8061, 9.4795) -> (18.7116, 9.7729)
  curve K24 (17.1001, 9.6415) -> (17.8061, 9.4795)
  curve K25 (16.5987, 10.1088) -> (17.1001, 9.6415)
  curve K26 (16.2884, 10.8523) -> (16.5987, 10.1088)
  curve K27 (16.1758, 12.0341) -> (16.2884, 10.8523)
  curve K28 (16.3566, 13.4546) -> (16.1758, 12.0341)
  curve K29 (16.8972, 14.2902) -> (16.3566, 13.4546)
  curve K30 (17.8061, 14.5853) -> (16.8972, 14.2902)
  line L5 (14.508, 14.5) -> (14.508, 13.8008)
  line L6 (15.2072, 14.5) -> (14.508, 14.5)
  line L7 (15.2072, 13.8008) -> (15.2072, 14.5)
  line L8 (14.508, 13.8008) -> (15.2072, 13.8008)
  curve K31 (10.9368, 22.8104) -> (11.9037, 22.4795)
  curve K32 (10.4849, 23.7244) -> (10.9368, 22.8104)
  line L9 (11.0954, 23.7722) -> (10.4849, 23.7244)
  curve K33 (11.3273, 23.2469) -> (11.0954, 23.7722)
  curve K34 (11.9412, 22.9843) -> (11.3273, 23.2469)
  curve K35 (12.4562, 23.148) -> (11.9412, 22.9843)
  curve K36 (12.9132, 23.7653) -> (12.4562, 23.148)
  curve K37 (13.0872, 24.9216) -> (12.9132, 23.7653)
  curve K38 (12.5449, 24.4202) -> (13.0872, 24.9216)
  curve K39 (11.873, 24.2565) -> (12.5449, 24.4202)
  curve K40 (10.8276, 24.7084) -> (11.873, 24.2565)
  curve K41 (10.3962, 25.8765) -> (10.8276, 24.7084)
  curve K42 (10.5991, 26.7514) -> (10.3962, 25.8765)
  curve K43 (11.1568, 27.3704) -> (10.5991, 26.7514)
  curve K44 (11.9617, 27.5853) -> (11.1568, 27.3704)
  curve K45 (13.2134, 27.0208) -> (11.9617, 27.5853)
  curve K46 (13.6977, 25.1603) -> (13.2134, 27.0208)
  curve K47 (13.1622, 23.0525) -> (13.6977, 25.1603)
  curve K48 (11.9037, 22.4795) -> (13.1622, 23.0525)
  curve K49 (18.9868, 39.5668) -> (17.851, 40.0853)
  curve K50 (19.4813, 37.5341) -> (18.9868, 39.5668)
  curve K51 (19.2989, 36.1068) -> (19.4813, 37.5341)
  curve K52 (18.7566, 35.2729) -> (19.2989, 36.1068)
  curve K53 (17.851, 34.9795) -> (18.7566, 35.2729)
  curve K54 (17.145, 35.1415) -> (17.851, 34.9795)
  curve K55 (16.6437, 35.6088) -> (17.145, 35.1415)
  curve K56 (16.3333, 36.3523) -> (16.6437, 35.6088)
  curve K57 (16.2208, 37.5341) -> (16.3333, 36.3523)
  curve K58 (16.4015, 38.9546) -> (16.2208, 37.5341)
  curve K59 (16.9421, 39.7902) -> (16.4015, 38.9546)
  curve K60 (17.851, 40.0853) -> (16.9421, 39.7902)
  line L10 (14.553, 40) -> (14.553, 39.3008)
  line L11 (15.2521, 40) -> (14.553, 40)
  line L12 (15.2521, 39.3008) -> (15.2521, 40)
  line L13 (14.553, 39.3008) -> (15.2521, 39.3008)
  curve K61 (13.3635, 51.5668) -> (12.2277, 52.0853)
  curve K62 (13.858, 49.5341) -> (13.3635, 51.5668)
  curve K63 (13.6755, 48.1068) -> (13.858, 49.5341)
  curve K64 (13.1332, 47.2729) -> (13.6755, 48.1068)
  curve K65 (12.2277, 46.9795) -> (13.1332, 47.2729)
  curve K66 (11.5217, 47.1415) -> (12.2277, 46.9795)
  curve K67 (11.0204, 47.6088) -> (11.5217, 47.1415)
  curve K68 (10.71, 48.3523) -> (11.0204, 47.6088)
  curve K69 (10.5974, 49.5341) -> (10.71, 48.3523)
  curve K70 (10.7782, 50.9546) -> (10.5974, 49.5341)
  curve K71 (11.3188, 51.7902) -> (10.7782, 50.9546)
  curve K72 (12.2277, 52.0853) -> (11.3188, 51.7902)
  line L14 (14.755, 52) -> (14.755, 51.3008)
  line L15 (15.4542, 52) -> (14.755, 52)
  line L16 (15.4542, 51.3008) -> (15.4542, 52)
  line L17 (14.755, 51.3008) -> (15.4542, 51.3008)
  line L18 (17.371, 46.9795) -> (17.7666, 46.9795)
  line L19 (17.371, 52) -> (17.371, 46.9795)
  line L20 (17.9849, 52) -> (17.371, 52)
  line L21 (17.9849, 48.088) -> (17.9849, 52)
  curve K73 (18.5664, 48.5109) -> (17.9849, 48.088)
  curve K74 (19.2127, 48.8281) -> (18.5664, 48.5109)
  line L22 (19.2127, 48.2347) -> (19.2127, 48.8281)
  curve K75 (18.3123, 47.648) -> (19.2127, 48.2347)
  curve K76 (17.7666, 46.9795) -> (18.3123, 47.648)
  curve K77 (13.4155, 37.737) -> (13.6628, 38.5539)
  curve K78 (12.7112, 37.2885) -> (13.4155, 37.737)
  curve K79 (13.2774, 36.8895) -> (12.7112, 37.2885)
  curve K80 (13.4615, 36.2688) -> (13.2774, 36.8895)
  curve K81 (13.0693, 35.3513) -> (13.4615, 36.2688)
  curve K82 (12.0257, 34.9795) -> (13.0693, 35.3513)
  curve K83 (10.9718, 35.3598) -> (12.0257, 34.9795)
  curve K84 (10.5727, 36.2858) -> (10.9718, 35.3598)
  curve K85 (10.7552, 36.8912) -> (10.5727, 36.2858)
  curve K86 (11.3094, 37.2885) -> (10.7552, 36.8912)
  curve K87 (10.6085, 37.7729) -> (11.3094, 37.2885)
  curve K88 (10.3681, 38.5709) -> (10.6085, 37.7729)
  curve K89 (10.8217, 39.6487) -> (10.3681, 38.5709)
  curve K90 (12.0154, 40.0853) -> (10.8217, 39.6487)
  curve K91 (13.2092, 39.647) -> (12.0154, 40.0853)
  curve K92 (13.6628, 38.5539) -> (13.2092, 39.647)
  line L23 (14.5674, 27.5) -> (14.5674, 26.8008)
  line L24 (15.2666, 27.5) -> (14.5674, 27.5)
  line L25 (15.2666, 26.8008) -> (15.2666, 27.5)
  line L26 (14.5674, 26.8008) -> (15.2666, 26.8008)
  curve K93 (19.0012, 27.0668) -> (17.8655, 27.5853)
  curve K94 (19.4958, 25.0341) -> (19.0012, 27.0668)
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  dimension "d101" Text1-Height = 2
  dimension "d102" Text2-Height = 2
  dimension "d103" Text3-Height = 2
  dimension "d104" Text4-Height = 2
  dimension "d105" Text5-Height = 2
  dimension "d106" Text6-Height = 2
extrude "Extrude18" cut sketch "Sketch16" against normal blind 0.5
move "Move10"
sketch "Sketch17" plane through (0, 0, 30) normal (0, 0, 1) x axis (-1, 0, 0)
  line L1 (-56, 57.8) -> (21, 57.8)
  line L2 (-57.8, -6) -> (-57.8, 56)
  line L3 (21, -7.8) -> (-56, -7.8)
  line L4 (22.8, 56) -> (22.8, -6)
  curve K1 (19.0314, 0.5668) -> (17.8956, 1.0853)
  curve K2 (19.5259, -1.4659) -> (19.0314, 0.5668)
  curve K3 (19.3435, -2.8932) -> (19.5259, -1.4659)
  curve K4 (18.8012, -3.7271) -> (19.3435, -2.8932)
  curve K5 (17.8956, -4.0205) -> (18.8012, -3.7271)
  curve K6 (17.1896, -3.8585) -> (17.8956, -4.0205)
  curve K7 (16.6883, -3.3912) -> (17.1896, -3.8585)
  curve K8 (16.3779, -2.6477) -> (16.6883, -3.3912)
  curve K9 (16.2653, -1.4659) -> (16.3779, -2.6477)
  curve K10 (16.4461, -0.0454) -> (16.2653, -1.4659)
  curve K11 (16.9867, 0.7902) -> (16.4461, -0.0454)
  curve K12 (17.8956, 1.0853) -> (16.9867, 0.7902)
  line L5 (14.5975, 1) -> (14.5975, 0.3008)
  line L6 (15.2967, 1) -> (14.5975, 1)
  line L7 (15.2967, 0.3008) -> (15.2967, 1)
  line L8 (14.5975, 0.3008) -> (15.2967, 0.3008)
  line L9 (11.0292, 14.5) -> (11.0292, 13.3029)
  line L10 (11.6431, 14.5) -> (11.0292, 14.5)
  line L11 (11.6431, 13.3029) -> (11.6431, 14.5)
  line L12 (13.8122, 13.3029) -> (11.6431, 13.3029)
  line L13 (13.8122, 12.7401) -> (13.8122, 13.3029)
  line L14 (11.5305, 9.5) -> (13.8122, 12.7401)
  line L15 (11.0292, 9.5) -> (11.5305, 9.5)
  line L16 (11.0292, 12.7401) -> (11.0292, 9.5)
  line L17 (10.3538, 12.7401) -> (11.0292, 12.7401)
  line L18 (10.3538, 13.3029) -> (10.3538, 12.7401)
  line L19 (11.0292, 13.3029) -> (10.3538, 13.3029)
  curve K13 (19.0012, 27.0668) -> (17.8655, 27.5853)
  curve K14 (19.4958, 25.0341) -> (19.0012, 27.0668)
  curve K15 (19.3133, 23.6068) -> (19.4958, 25.0341)
  curve K16 (18.771, 22.7729) -> (19.3133, 23.6068)
  curve K17 (17.8655, 22.4795) -> (18.771, 22.7729)
  curve K18 (17.1595, 22.6415) -> (17.8655, 22.4795)
  curve K19 (16.6581, 23.1088) -> (17.1595, 22.6415)
  curve K20 (16.3478, 23.8523) -> (16.6581, 23.1088)
  curve K21 (16.2352, 25.0341) -> (16.3478, 23.8523)
  curve K22 (16.416, 26.4546) -> (16.2352, 25.0341)
  curve K23 (16.9566, 27.2902) -> (16.416, 26.4546)
  curve K24 (17.8655, 27.5853) -> (16.9566, 27.2902)
  line L20 (14.5674, 27.5) -> (14.5674, 26.8008)
  line L21 (15.2666, 27.5) -> (14.5674, 27.5)
  line L22 (15.2666, 26.8008) -> (15.2666, 27.5)
  line L23 (14.5674, 26.8008) -> (15.2666, 26.8008)
  curve K25 (13.4155, 37.737) -> (13.6628, 38.5539)
  curve K26 (12.7112, 37.2885) -> (13.4155, 37.737)
  curve K27 (13.2774, 36.8895) -> (12.7112, 37.2885)
  curve K28 (13.4615, 36.2688) -> (13.2774, 36.8895)
  curve K29 (13.0693, 35.3513) -> (13.4615, 36.2688)
  curve K30 (12.0257, 34.9795) -> (13.0693, 35.3513)
  curve K31 (10.9718, 35.3598) -> (12.0257, 34.9795)
  curve K32 (10.5727, 36.2858) -> (10.9718, 35.3598)
  curve K33 (10.7552, 36.8912) -> (10.5727, 36.2858)
  curve K34 (11.3094, 37.2885) -> (10.7552, 36.8912)
  curve K35 (10.6085, 37.7729) -> (11.3094, 37.2885)
  curve K36 (10.3681, 38.5709) -> (10.6085, 37.7729)
  curve K37 (10.8217, 39.6487) -> (10.3681, 38.5709)
  curve K38 (12.0154, 40.0853) -> (10.8217, 39.6487)
  curve K39 (13.2092, 39.647) -> (12.0154, 40.0853)
  curve K40 (13.6628, 38.5539) -> (13.2092, 39.647)
  line L24 (17.371, 46.9795) -> (17.7666, 46.9795)
  line L25 (17.371, 52) -> (17.371, 46.9795)
  line L26 (17.9849, 52) -> (17.371, 52)
  line L27 (17.9849, 48.088) -> (17.9849, 52)
  curve K41 (18.5664, 48.5109) -> (17.9849, 48.088)
  curve K42 (19.2127, 48.8281) -> (18.5664, 48.5109)
  line L28 (19.2127, 48.2347) -> (19.2127, 48.8281)
  curve K43 (18.3123, 47.648) -> (19.2127, 48.2347)
  curve K44 (17.7666, 46.9795) -> (18.3123, 47.648)
  line L29 (14.755, 52) -> (14.755, 51.3008)
  line L30 (15.4542, 52) -> (14.755, 52)
  line L31 (15.4542, 51.3008) -> (15.4542, 52)
  line L32 (14.755, 51.3008) -> (15.4542, 51.3008)
  curve K45 (13.3635, 51.5668) -> (12.2277, 52.0853)
  curve K46 (13.858, 49.5341) -> (13.3635, 51.5668)
  curve K47 (13.6755, 48.1068) -> (13.858, 49.5341)
  curve K48 (13.1332, 47.2729) -> (13.6755, 48.1068)
  curve K49 (12.2277, 46.9795) -> (13.1332, 47.2729)
  curve K50 (11.5217, 47.1415) -> (12.2277, 46.9795)
  curve K51 (11.0204, 47.6088) -> (11.5217, 47.1415)
  curve K52 (10.71, 48.3523) -> (11.0204, 47.6088)
  curve K53 (10.5974, 49.5341) -> (10.71, 48.3523)
  curve K54 (10.7782, 50.9546) -> (10.5974, 49.5341)
  curve K55 (11.3188, 51.7902) -> (10.7782, 50.9546)
  curve K56 (12.2277, 52.0853) -> (11.3188, 51.7902)
  line L33 (14.553, 40) -> (14.553, 39.3008)
  line L34 (15.2521, 40) -> (14.553, 40)
  line L35 (15.2521, 39.3008) -> (15.2521, 40)
  line L36 (14.553, 39.3008) -> (15.2521, 39.3008)
  curve K57 (18.9868, 39.5668) -> (17.851, 40.0853)
  curve K58 (19.4813, 37.5341) -> (18.9868, 39.5668)
  curve K59 (19.2989, 36.1068) -> (19.4813, 37.5341)
  curve K60 (18.7566, 35.2729) -> (19.2989, 36.1068)
  curve K61 (17.851, 34.9795) -> (18.7566, 35.2729)
  curve K62 (17.145, 35.1415) -> (17.851, 34.9795)
  curve K63 (16.6437, 35.6088) -> (17.145, 35.1415)
  curve K64 (16.3333, 36.3523) -> (16.6437, 35.6088)
  curve K65 (16.2208, 37.5341) -> (16.3333, 36.3523)
  curve K66 (16.4015, 38.9546) -> (16.2208, 37.5341)
  curve K67 (16.9421, 39.7902) -> (16.4015, 38.9546)
  curve K68 (17.851, 40.0853) -> (16.9421, 39.7902)
  curve K69 (10.9368, 22.8104) -> (11.9037, 22.4795)
  curve K70 (10.4849, 23.7244) -> (10.9368, 22.8104)
  line L37 (11.0954, 23.7722) -> (10.4849, 23.7244)
  curve K71 (11.3273, 23.2469) -> (11.0954, 23.7722)
  curve K72 (11.9412, 22.9843) -> (11.3273, 23.2469)
  curve K73 (12.4562, 23.148) -> (11.9412, 22.9843)
  curve K74 (12.9132, 23.7653) -> (12.4562, 23.148)
  curve K75 (13.0872, 24.9216) -> (12.9132, 23.7653)
  curve K76 (12.5449, 24.4202) -> (13.0872, 24.9216)
  curve K77 (11.873, 24.2565) -> (12.5449, 24.4202)
  curve K78 (10.8276, 24.7084) -> (11.873, 24.2565)
  curve K79 (10.3962, 25.8765) -> (10.8276, 24.7084)
  curve K80 (10.5991, 26.7514) -> (10.3962, 25.8765)
  curve K81 (11.1568, 27.3704) -> (10.5991, 26.7514)
  curve K82 (11.9617, 27.5853) -> (11.1568, 27.3704)
  curve K83 (13.2134, 27.0208) -> (11.9617, 27.5853)
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  point P5 (-56, 56)
  point P317 (-56, 56)
  coincident P5 P317
extrude "Extrude19" cut sketch "Sketch17" against normal blind 2
extrude "Extrude20" cut of existing geometry blind -2.5
extrude "Extrude21" cut sketch "Sketch17" against normal blind 2
extrude "Extrude22" cut of existing geometry blind -0.5
extrude "Extrude23" cut of existing geometry blind -1
extrude "Extrude24" cut of existing geometry blind -2.5
named bodies: "Body", "Lid"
